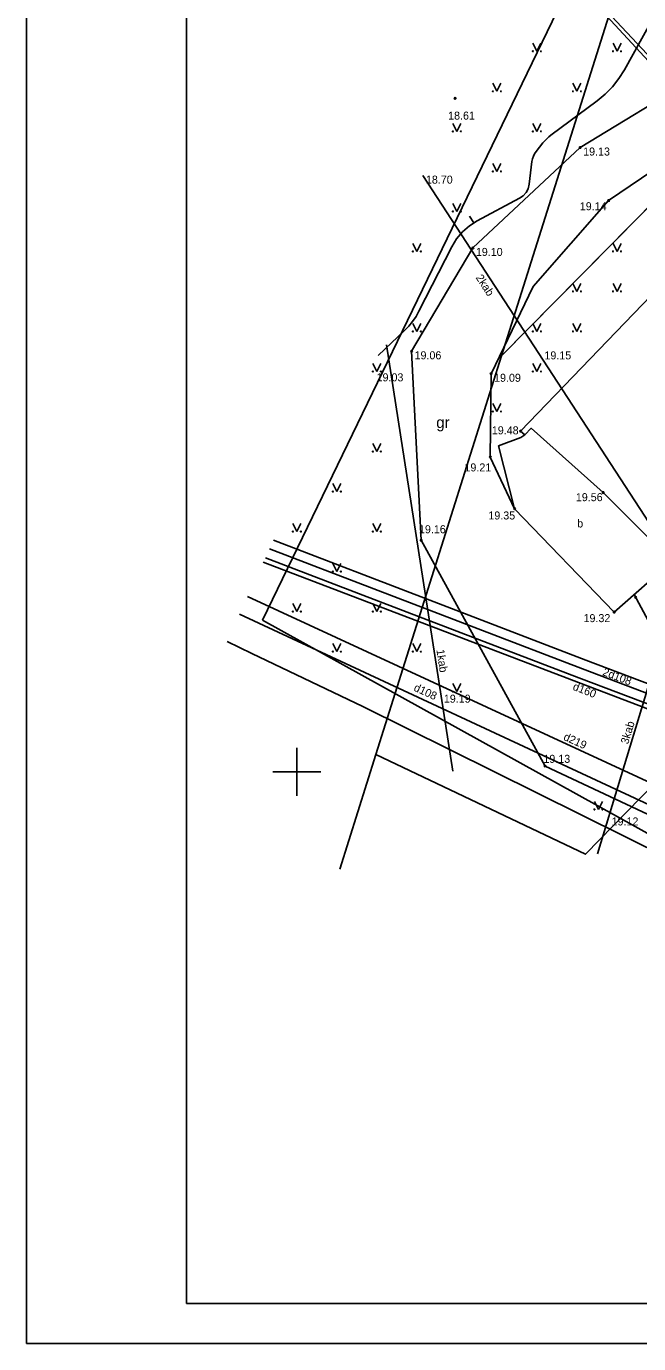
# Model space of a CAD drawing. Extents: x 532933 to 533143, y 328014 to 328163.
# Drawn here: x 532933.1 to 532971.4, y 328014.3 to 328096.6 of the extents above; entities that cross this region are included whole.
import ezdxf

# ---------------------------------------------------------------- set-up
doc = ezdxf.new("R2010")
doc.units = 0
for name, color, linetype in [('BUVE_BDET_####_####_#', 7, 'Continuous'), ('BUVE_BDET_####_TKST_#', 7, 'Continuous'), ('BUVE_EKAS_####_####_#', 7, 'Continuous'), ('CELI_CMAL_####_####_#', 7, 'Continuous'), ('CELI_CSEG_####_TKST_#', 7, 'Continuous'), ('ELEK_VADP_ZSPR_####_#', 7, 'Continuous'), ('GAZE_VADP_ASP1_####_I', 7, 'Continuous'), ('GAZE_VADP_ASP1_TKST_I', 7, 'Continuous'), ('GAZE_VADP_NEDR_####_#', 7, 'Continuous'), ('GAZE_VADP_NEDR_TKST_#', 7, 'Continuous'), ('GAZE_VADP_ZSPD_####_#', 7, 'Continuous'), ('GEOD_ELEM_####_####_#', 7, 'Continuous'), ('RAMI_PLAN_####_TKST_#', 7, 'Continuous'), ('RAMI_UZMR_####_####_#', 7, 'Continuous'), ('RELJ_AATZ_####_TKST_#', 7, 'Continuous'), ('RELJ_ELEM_####_####_#', 7, 'Continuous'), ('RELJ_HORZ_PAMT_####_#', 7, 'Continuous'), ('ROBZ_UZMR_####_####_#', 7, 'Continuous'), ('SAKT_VADV_PKAB_####_#', 7, 'Continuous'), ('SAKT_VADV_PKAB_TKST_#', 7, 'Continuous'), ('SILT_VADP_UDEN_####_#', 7, 'Continuous'), ('SILT_VADP_UDEN_TKAM_#', 7, 'Continuous'), ('SILT_VADP_UDEN_TKST_#', 7, 'Continuous'), ('TERT_ELEM_####_####_#', 7, 'Continuous'), ('UDTK_VADP_UDEN_####_#', 7, 'Continuous'), ('UDTK_VADP_UDEN_TKST_#', 7, 'Continuous')]:
    doc.layers.add(name, color=color, linetype=linetype)

msp = doc.modelspace()

# ---------------------------------------------------------------- linework, layer by layer
at = {"layer": 'BUVE_BDET_####_####_#'}
msp.add_line((532964.233, 328071.04), (532963.994, 328070.869), dxfattribs=at)
msp.add_lwpolyline([(532973.427, 328063.138), (532969.826, 328059.969), (532963.605, 328066.425), (532962.603, 328070.346), (532963.994, 328070.869)], dxfattribs=at)
at = {"layer": 'BUVE_EKAS_####_####_#'}
for p, q in [((532977.471, 328085.314), (532963.98, 328071.276)), ((532963.98, 328071.276), (532964.233, 328071.04))]:
    msp.add_line(p, q, dxfattribs=at)
msp.add_lwpolyline([(532964.233, 328071.04), (532964.63, 328071.455), (532969.135, 328067.437), (532973.381, 328063.184)], dxfattribs=at)
at = {"layer": 'CELI_CMAL_####_####_#'}
for points in [[(532960.996, 328082.718), (532967.7, 328088.991), (532974.969, 328093.406), (532984.293, 328097.298), (532999.014, 328101.642), (533000, 328101.952)], [(532998.947, 328084.318), (532991.789, 328095.063), (532982.013, 328092.735), (532974.31, 328088.941), (532969.478, 328085.677), (532964.771, 328080.302), (532962.135, 328074.858), (532962.083, 328069.653)], [(532960.996, 328082.718), (532957.166, 328076.262)], [(533000, 328031.505), (532994.447, 328035.097), (532978.349, 328044.324), (532965.504, 328050.351), (532957.768, 328064.457), (532957.166, 328076.262)], [(532962.083, 328069.653), (532963.605, 328066.425)], [(532971.073, 328061.066), (532974.996, 328053.804), (532983.457, 328045.647), (532997.471, 328037.127), (533000, 328035.732)]]:
    msp.add_lwpolyline(points, dxfattribs=at)
at = {"layer": 'ELEK_VADP_ZSPR_####_#'}
for points in [[(532985.737, 328079.805), (532977.556, 328088.778), (532968.408, 328098.547), (532965.686, 328099.193)], [(532965.739, 328098.982), (532968.304, 328098.364), (532985.598, 328079.659)]]:
    msp.add_lwpolyline(points, dxfattribs=at)
at = {"layer": 'GAZE_VADP_ASP1_####_I'}
msp.add_line((532984.115, 328043.743), (532946.921, 328060.941), dxfattribs=at)
at = {"layer": 'GAZE_VADP_NEDR_####_#'}
msp.add_line((532982.828, 328042.889), (532946.421, 328059.848), dxfattribs=at)
at = {"layer": 'GAZE_VADP_ZSPD_####_#'}
for p, q in [((532947.187, 328057.387), (532954.128, 328054.064)), ((532954.128, 328054.064), (532985.007, 328038.734))]:
    msp.add_line(p, q, dxfattribs=at)
msp.add_lwpolyline([(532945.634, 328058.13), (532947.187, 328057.387)], dxfattribs=at)
at = {"layer": 'GEOD_ELEM_####_####_#'}
for p, q in [((532950, 328051.5), (532950, 328050)), ((532948.5, 328050), (532950, 328050)), ((532950, 328050), (532950, 328048.5)), ((532950, 328050), (532951.5, 328050))]:
    msp.add_line(p, q, dxfattribs=at)
at = {"layer": 'RAMI_PLAN_####_TKST_#'}
for p, q in [((532933.097, 328162.773), (532933.097, 328014.273)), ((532943.097, 328016.773), (532943.097, 328160.273)), ((533140.597, 328016.773), (532943.097, 328016.773)), ((532933.097, 328014.273), (533143.097, 328014.273))]:
    msp.add_line(p, q, dxfattribs=at)
at = {"layer": 'RAMI_UZMR_####_####_#'}
msp.add_lwpolyline([(532947.854, 328059.458), (532970.012, 328105.269), (532980.164, 328130.66), (532983.041, 328140.509), (533003.397, 328153.917), (533034.71, 328122.623), (533045.001, 328112.629), (533020.332, 328088.009), (533039.378, 328069.977), (533029.682, 328029.753), (533016.724, 328021.343), (532947.854, 328059.458)], dxfattribs=at)
at = {"layer": 'RELJ_ELEM_####_####_#'}
for centre in [(532959.886, 328092.063), (532967.7, 328088.991), (532969.478, 328085.677), (532960.996, 328082.718), (532957.166, 328076.262), (532962.135, 328074.858), (532963.98, 328071.275), (532962.083, 328069.653), (532969.135, 328067.437), (532963.605, 328066.425), (532957.768, 328064.457), (532971.166, 328060.892), (532969.826, 328059.969), (532965.504, 328050.351)]:
    msp.add_circle(centre, 0.05, dxfattribs=at)
at = {"layer": 'RELJ_HORZ_PAMT_####_#'}
msp.add_line((532960.792, 328084.7), (532961.059, 328084.278), dxfattribs=at)
msp.add_lwpolyline([(532974.68, 328101.466), (532970.462, 328093.847), (532970.117, 328093.294), (532969.719, 328092.786), (532969.269, 328092.324), (532968.766, 328091.908), (532965.87, 328089.758), (532965.734, 328089.651), (532965.607, 328089.535), (532965.487, 328089.411), (532965.376, 328089.278), (532964.945, 328088.733), (532964.849, 328088.592), (532964.773, 328088.442), (532964.719, 328088.283), (532964.686, 328088.115), (532964.505, 328086.691), (532964.439, 328086.415), (532964.317, 328086.178), (532964.14, 328085.98), (532963.906, 328085.821), (532961.27, 328084.411), (532960.775, 328084.098), (532960.344, 328083.722), (532959.977, 328083.284), (532959.674, 328082.783), (532957.629, 328078.767), (532957.444, 328078.439), (532957.232, 328078.13), (532956.995, 328077.84), (532956.732, 328077.57), (532955.074, 328076.006)], dxfattribs=at)
at = {"layer": 'ROBZ_UZMR_####_####_#'}
for p, q in [((532984.275, 328144.093), (532962.791, 328075.982)), ((532977.358, 328090.737), (532962.791, 328075.982)), ((532962.791, 328075.982), (532954.932, 328051.068))]:
    msp.add_line(p, q, dxfattribs=at)
msp.add_lwpolyline([(532954.932, 328051.068), (532962.791, 328075.982), (532977.358, 328090.737), (532984.352, 328083.929), (532990.879, 328090.61), (533001.874, 328079.871), (532999.253, 328076.841), (532993.949, 328071.405), (532979.271, 328056.364), (532968.026, 328044.841)], close=True, dxfattribs=at)
msp.add_lwpolyline([(532952.676, 328043.916), (532954.932, 328051.068), (532968.026, 328044.841), (532979.271, 328056.364), (532998.604, 328038.086), (533020.389, 328026.352), (533032.36, 328019.904)], dxfattribs=at)
at = {"layer": 'SAKT_VADV_PKAB_####_#'}
for p, q in [((532957.876, 328087.235), (532974.079, 328062.362)), ((532955.591, 328076.661), (532959.74, 328050.038)), ((532974.079, 328062.362), (532968.787, 328044.862))]:
    msp.add_line(p, q, dxfattribs=at)
at = {"layer": 'SILT_VADP_UDEN_####_#'}
msp.add_line((533000, 328044.239), (532967.835, 328056.416), dxfattribs=at)
msp.add_lwpolyline([(532967.835, 328056.416), (532948.283, 328063.917)], dxfattribs=at)
at = {"layer": 'SILT_VADP_UDEN_TKAM_#'}
for p, q in [((532958.307, 328060.714), (532948.533, 328064.464)), ((532957.878, 328059.593), (532948.032, 328063.37))]:
    msp.add_line(p, q, dxfattribs=at)
for points in [[(532986.087, 328050.147), (532968.048, 328056.976), (532958.307, 328060.714)], [(532985.663, 328049.025), (532967.621, 328055.855), (532957.878, 328059.593)]]:
    msp.add_lwpolyline(points, dxfattribs=at)
at = {"layer": 'TERT_ELEM_####_####_#'}
for p, q in [((532964.75, 328095.5), (532965, 328095)), ((532965, 328095), (532965.25, 328095.5)), ((532969.75, 328095.5), (532970, 328095)), ((532970, 328095), (532970.25, 328095.5)), ((532962.25, 328093), (532962.5, 328092.5)), ((532962.5, 328092.5), (532962.75, 328093)), ((532967.25, 328093), (532967.5, 328092.5)), ((532967.5, 328092.5), (532967.75, 328093)), ((532959.75, 328090.5), (532960, 328090)), ((532960, 328090), (532960.25, 328090.5)), ((532964.75, 328090.5), (532965, 328090)), ((532965, 328090), (532965.25, 328090.5)), ((532962.25, 328088), (532962.5, 328087.5)), ((532962.5, 328087.5), (532962.75, 328088)), ((532959.75, 328085.5), (532960, 328085)), ((532960, 328085), (532960.25, 328085.5)), ((532957.25, 328083), (532957.5, 328082.5)), ((532957.5, 328082.5), (532957.75, 328083)), ((532969.75, 328083), (532970, 328082.5)), ((532970, 328082.5), (532970.25, 328083)), ((532967.25, 328080.5), (532967.5, 328080)), ((532967.5, 328080), (532967.75, 328080.5)), ((532969.75, 328080.5), (532970, 328080)), ((532970, 328080), (532970.25, 328080.5)), ((532957.25, 328078), (532957.5, 328077.5)), ((532957.5, 328077.5), (532957.75, 328078)), ((532964.75, 328078), (532965, 328077.5)), ((532965, 328077.5), (532965.25, 328078)), ((532967.25, 328078), (532967.5, 328077.5)), ((532967.5, 328077.5), (532967.75, 328078)), ((532954.75, 328075.5), (532955, 328075)), ((532955, 328075), (532955.25, 328075.5)), ((532964.75, 328075.5), (532965, 328075)), ((532965, 328075), (532965.25, 328075.5)), ((532962.25, 328073), (532962.5, 328072.5)), ((532962.5, 328072.5), (532962.75, 328073)), ((532954.75, 328070.5), (532955, 328070)), ((532955, 328070), (532955.25, 328070.5)), ((532952.25, 328068), (532952.5, 328067.5)), ((532952.5, 328067.5), (532952.75, 328068)), ((532949.75, 328065.5), (532950, 328065)), ((532950, 328065), (532950.25, 328065.5)), ((532954.75, 328065.5), (532955, 328065)), ((532955, 328065), (532955.25, 328065.5)), ((532952.25, 328063), (532952.5, 328062.5)), ((532952.5, 328062.5), (532952.75, 328063)), ((532949.75, 328060.5), (532950, 328060)), ((532950, 328060), (532950.25, 328060.5)), ((532954.75, 328060.5), (532955, 328060)), ((532955, 328060), (532955.25, 328060.5)), ((532952.25, 328058), (532952.5, 328057.5)), ((532952.5, 328057.5), (532952.75, 328058)), ((532957.25, 328058), (532957.5, 328057.5)), ((532957.5, 328057.5), (532957.75, 328058)), ((532959.75, 328055.5), (532960, 328055)), ((532960, 328055), (532960.25, 328055.5)), ((532968.587, 328048.144), (532968.837, 328047.644)), ((532968.837, 328047.644), (532969.087, 328048.144))]:
    msp.add_line(p, q, dxfattribs=at)
for centre, radius in [((532964.75, 328095), 0.028), ((532965.25, 328095), 0.0263), ((532969.75, 328095), 0.028), ((532970.25, 328095), 0.0263), ((532962.25, 328092.5), 0.028), ((532962.75, 328092.5), 0.0263), ((532967.25, 328092.5), 0.028), ((532967.75, 328092.5), 0.0263), ((532959.75, 328090), 0.028), ((532960.25, 328090), 0.0263), ((532964.75, 328090), 0.028), ((532965.25, 328090), 0.0263), ((532962.25, 328087.5), 0.028), ((532962.75, 328087.5), 0.0263), ((532959.75, 328085), 0.028), ((532960.25, 328085), 0.0263), ((532957.25, 328082.5), 0.028), ((532957.75, 328082.5), 0.0263), ((532969.75, 328082.5), 0.028), ((532970.25, 328082.5), 0.0263), ((532967.25, 328080), 0.028), ((532967.75, 328080), 0.0263), ((532969.75, 328080), 0.028), ((532970.25, 328080), 0.0263), ((532957.25, 328077.5), 0.028), ((532957.75, 328077.5), 0.0263), ((532964.75, 328077.5), 0.028), ((532965.25, 328077.5), 0.0263), ((532967.25, 328077.5), 0.028), ((532967.75, 328077.5), 0.0263), ((532954.75, 328075), 0.028), ((532955.25, 328075), 0.0263), ((532964.75, 328075), 0.028), ((532965.25, 328075), 0.0263), ((532962.25, 328072.5), 0.028), ((532962.75, 328072.5), 0.0263), ((532954.75, 328070), 0.028), ((532955.25, 328070), 0.0263), ((532952.25, 328067.5), 0.028), ((532952.75, 328067.5), 0.0263), ((532949.75, 328065), 0.028), ((532950.25, 328065), 0.0263), ((532954.75, 328065), 0.028), ((532955.25, 328065), 0.0263), ((532952.25, 328062.5), 0.028), ((532952.75, 328062.5), 0.0263), ((532949.75, 328060), 0.028), ((532950.25, 328060), 0.0263), ((532954.75, 328060), 0.028), ((532955.25, 328060), 0.0263), ((532952.25, 328057.5), 0.028), ((532952.75, 328057.5), 0.0263), ((532957.25, 328057.5), 0.028), ((532957.75, 328057.5), 0.0263), ((532959.75, 328055), 0.028), ((532960.25, 328055), 0.0263), ((532968.587, 328047.643), 0.028), ((532969.087, 328047.643), 0.0263)]:
    msp.add_circle(centre, radius, dxfattribs=at)
at = {"layer": 'UDTK_VADP_UDEN_####_#'}
msp.add_line((532982.048, 328050.046), (532947.902, 328063.085), dxfattribs=at)

# ---------------------------------------------------------------- texts
at = {"layer": 'BUVE_BDET_####_TKST_#'}
msp.add_text(' b', height=0.5, dxfattribs=at).set_placement((532967.326, 328065.257))
at = {"layer": 'CELI_CSEG_####_TKST_#'}
msp.add_text('gr', height=0.7, dxfattribs=at).set_placement((532958.708, 328071.471))
at = {"layer": 'GAZE_VADP_ASP1_TKST_I'}
msp.add_text('d219', height=0.5, rotation=335.57682, dxfattribs=at).set_placement((532966.607, 328052.007))
at = {"layer": 'GAZE_VADP_NEDR_TKST_#'}
msp.add_text('d108', height=0.5, rotation=335.27057, dxfattribs=at).set_placement((532957.256, 328055.083))
at = {"layer": 'RELJ_AATZ_####_TKST_#'}
for s, p in [(' 18.61', (532959.263, 328090.733)), (' 19.13', (532967.7, 328088.491)), (' 18.70', (532957.876, 328086.735)), (' 19.14', (532967.488, 328085.072)), (' 19.10', (532960.996, 328082.218)), (' 19.06', (532957.166, 328075.762)), (' 19.15', (532965.28, 328075.756)), (' 19.03', (532954.794, 328074.384)), (' 19.09', (532962.135, 328074.358)), (' 19.48', (532961.994, 328071.074)), (' 19.21', (532960.283, 328068.757)), (' 19.56', (532967.243, 328066.899)), (' 19.35', (532961.778, 328065.756)), (' 19.16', (532957.441, 328064.895)), (' 19.32', (532967.723, 328059.343)), (' 19.19', (532958.996, 328054.311)), (' 19.13', (532965.216, 328050.554)), (' 19.12', (532969.477, 328046.644))]:
    msp.add_text(s, height=0.5, dxfattribs=at).set_placement(p)
at = {"layer": 'SAKT_VADV_PKAB_TKST_#'}
for s, rotation, p in [('2kab', 303.08024, (532961.15, 328080.867)), ('1kab', 278.85714, (532958.713, 328057.605)), ('3kab', 73.17317, (532970.693, 328051.683))]:
    msp.add_text(s, height=0.5, rotation=rotation, dxfattribs=at).set_placement(p)
at = {"layer": 'SILT_VADP_UDEN_TKST_#'}
msp.add_text('2d108', height=0.5, rotation=339.26497, dxfattribs=at).set_placement((532969.056, 328056.042))
at = {"layer": 'UDTK_VADP_UDEN_TKST_#'}
msp.add_text('d160', height=0.5, rotation=338.5427, dxfattribs=at).set_placement((532967.194, 328055.134))

doc.saveas('drawing.dxf')
